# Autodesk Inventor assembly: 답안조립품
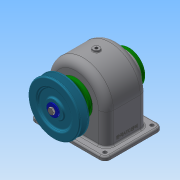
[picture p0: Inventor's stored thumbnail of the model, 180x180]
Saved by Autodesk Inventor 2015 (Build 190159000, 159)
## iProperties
Created: 2022-09
Part Number: 답안조립품
Document SubType Name: Assembly
Designer: 학생용
Author: 학생용
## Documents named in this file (16)
- C:\Users\학생용\Desktop\720906V1021\답안조립품.iam
- C:\Users\학생용\Desktop\720906V1021\1본체.ipt
- C:\Users\학생용\Desktop\720906V1021\V-벨트풀리.ipt
- C:\Users\학생용\Desktop\720906V1021\뒤커버.ipt
- C:\Users\학생용\Desktop\720906V1021\멈춤나사 M4 x 10.ipt
- C:\Users\학생용\Desktop\720906V1021\베어링 6203.ipt
- C:\Users\학생용\Desktop\720906V1021\볼트 M3 x 10.ipt
- C:\Users\학생용\Desktop\720906V1021\스퍼기어.ipt
- C:\Users\학생용\Desktop\720906V1021\앞커버.ipt
- C:\Users\학생용\Desktop\720906V1021\오일 실 17 x 30 x 8.ipt
- C:\Users\학생용\Desktop\720906V1021\와셔 6 x 22.ipt
- C:\Users\학생용\Desktop\720906V1021\육각머리볼트 M3 x 8.ipt
- C:\Users\학생용\Desktop\720906V1021\축.ipt
- C:\Users\학생용\Desktop\720906V1021\칼라.ipt
- C:\Users\학생용\Desktop\720906V1021\키 5 x 5 x 18.ipt
- C:\Users\학생용\Desktop\720906V1021\키 6 x 6 x 22.ipt
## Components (10 placed, 3 different names)
1. 1본체:1
2. V-벨트풀리:1 — 플러쉬:1
3. ISO 4762 M3 x 10:1
4. ISO 4762 M3 x 10:2
5. ISO 4762 M3 x 10:3
6. ISO 4762 M3 x 10:4
7. ISO 4762 M3 x 10:5
8. ISO 4762 M3 x 10:6
9. ISO 4762 M3 x 10:7
10. ISO 4762 M3 x 10:8
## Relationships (1: Flush 1)
- 플러쉬:1 [Flush]: V-벨트풀리:1
